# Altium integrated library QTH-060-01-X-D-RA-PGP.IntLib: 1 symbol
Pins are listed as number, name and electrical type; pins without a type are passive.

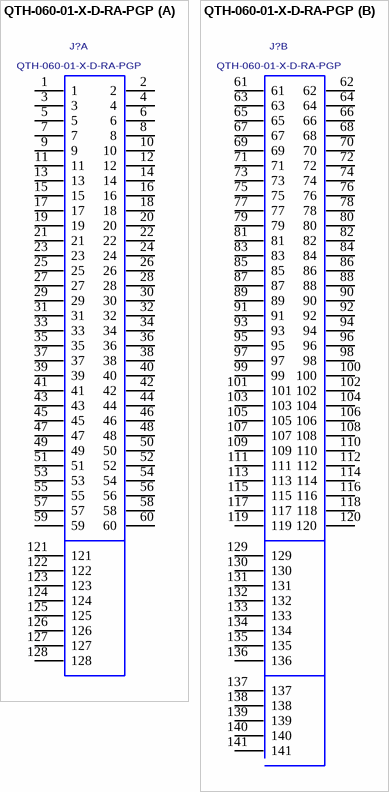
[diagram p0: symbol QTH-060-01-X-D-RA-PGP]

## QTH-060-01-X-D-RA-PGP
designator J?
RIGHT ANGLE TERMINAL STRIP, .5mm PITCH, 120 PINS.; MANUFACTURER: SAMTEC
footprint QTH-060-01-X-D-RA-PGP
part A pins: 1, 2, 3, 4, 5, 6, 7, 8, 9, 10, 11, 12, 13, 14, 15, 16, 17, 18, 19, 20, 21, 22, 23, 24, 25, 26, 27, 28, 29, 30, 31, 32, 33, 34, 35, 36, 37, 38, 39, 40, 41, 42, 43, 44, 45, 46, 47, 48, 49, 50, 51, 52, 53, 54, 55, 56, 57, 58, 59, 60, 121, 122, 123, 124, 125, 126, 127, 128
part B pins: 61, 62, 63, 64, 65, 66, 67, 68, 69, 70, 71, 72, 73, 74, 75, 76, 77, 78, 79, 80, 81, 82, 83, 84, 85, 86, 87, 88, 89, 90, 91, 92, 93, 94, 95, 96, 97, 98, 99, 100, 101, 102, 103, 104, 105, 106, 107, 108, 109, 110, 111, 112, 113, 114, 115, 116, 117, 118, 119, 120, 129, 130, 131, 132, 133, 134, 135, 136, 137, 138, 139, 140, 141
